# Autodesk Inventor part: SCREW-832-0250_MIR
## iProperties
Created: 2007-08
Part Number: SCREW-832-0250_MIR
Material: Stainless Steel
Document SubType Name: Modeling
Density: 8.08 g/cm^3
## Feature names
1. Derived Body1 [Tagging]
